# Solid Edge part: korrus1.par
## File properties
Author: Indrek
Template: Normal.par
Last saved by: Indrek
Revision: 14
Application: Solid Edge
Density: 7750,000 kg/m^3
Accuracy: 0,990
Material: Stainless Steel, 420
Face Style: Steel
Fill Style: ANSI32(Steel)
Virtual Style: Stainless steel
Coef. of Thermal Exp: 1e-05
Thermal Conductivity: 25.0
Specific Heat: 502.0
Modulus of Elasticity: 19994795300.0
Poission's Ratio: 0.29
Yield Stress: 344737850.0
Ultimate Stress: 655001915.0
Elongation: 0.0
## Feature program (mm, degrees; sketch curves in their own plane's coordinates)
make body feature "unnamed MakeBodyFeature 1"
sketch for "ExtrudedProtrusion_1" plane through (0, -392.2606, -246.4564) normal (0, -1, 0) x-axis (1, 0, 0)
  line (-90.7432, 47.25) -> (90.7431, 47.25)
extrude "ExtrudedProtrusion_1" add finite 189.0147 along +normal
sketch for "ExtrudedCutout_3" plane through (0, -290.6352, -199.2064) normal (0, 0, 1) x-axis (-1, 0, 0)
  line (145.5469, 330.1731) -> (178.3941, 235.8643)
  line (178.3941, 235.8643) -> (98.2107, 226.7853)
  line (-160.2715, 235.8643) -> (-98.1997, 222.207)
  line (-160.2715, 235.8643) -> (-57, 370.9489)
  line (-57, 370.9489) -> (145.5469, 330.1731)
extrude "ExtrudedCutout_3" cut finite 101.9235 along -normal
fillet "Round_2" radius 10
sketch used by "ExtrudedCutout_4" plane through (0, 0, -246.4564) normal (0, 1, 0) x-axis (-1, 0, 0)
extrude "ExtrudedCutout_4" cut finite 610.0099 along -normal
lofted protrusion "LoftedProtrusion_1"  StartTangentMagnitude1 = 1; EndTangentMagnitude1 = 1
sketch for "unnamed Cutout 1" #1 plane through (0, 0, -199.2064) normal (0, 0, -1) x-axis (0, 1, 0)
  line (260, 79.8569) -> (260, 10.0062)
  line (210, 10.0062) -> (260, 10.0062)
  line (210, 79.8569) -> (210, 10.0062)
  line (260, 79.8569) -> (210, 79.8569)
sketch for "unnamed Cutout 1" #2 plane through (0, 0, -199.2064) normal (0, 0, -1) x-axis (0, 1, 0)
  line (260, -79.8445) -> (260, -9.9938)
  line (210, -9.9938) -> (260, -9.9938)
  line (210, -79.8445) -> (210, -9.9938)
  line (260, -79.8445) -> (210, -79.8445)
sketch for "unnamed Cutout 1" #3 plane through (0, 0, -199.2064) normal (0, 0, -1) x-axis (0, 1, 0)
  line (190, -79.8445) -> (190, -9.9938)
  line (140, -9.9938) -> (190, -9.9938)
  line (140, -79.8445) -> (140, -9.9938)
  line (190, -79.8445) -> (140, -79.8445)
sketch for "unnamed Cutout 1" #4 plane through (0, 0, -199.2064) normal (0, 0, -1) x-axis (0, 1, 0)
  line (190, 79.8569) -> (190, 10.0062)
  line (140, 10.0062) -> (190, 10.0062)
  line (140, 10.0062) -> (140, 79.8569)
  line (190, 79.8569) -> (140, 79.8569)
sketch for "unnamed Cutout 1" #5 plane through (0, 0, -199.2064) normal (0, 0, -1) x-axis (0, 1, 0)
  line (120, 79.8569) -> (120, 10.0062)
  line (70, 10.0062) -> (120, 10.0062)
  line (70, 79.8569) -> (70, 10.0062)
  line (120, 79.8569) -> (70, 79.8569)
sketch for "unnamed Cutout 1" #6 plane through (0, 0, -199.2064) normal (0, 0, -1) x-axis (0, 1, 0)
  line (120, -79.8445) -> (120, -9.9938)
  line (70, -9.9938) -> (120, -9.9938)
  line (70, -79.8445) -> (70, -9.9938)
  line (120, -79.8445) -> (70, -79.8445)
extrude "unnamed Cutout 1" cut along +normal
sketch for "ExtrudedCutout_12" #1 plane through (0, 0, -199.2064) normal (0, 0, -1) x-axis (0, 1, 0)
  line (120, 79.8569) -> (120, 155.8794)
  line (120, 155.8794) -> (70, 155.8794)
  line (70, 155.8794) -> (70, 79.8569)
  line (70, 79.8569) -> (120, 79.8569)
sketch for "ExtrudedCutout_12" #2 plane through (0, 0, -199.2064) normal (0, 0, -1) x-axis (0, 1, 0)
  line (140, 79.8569) -> (140, 155.1744)
  line (140, 155.1744) -> (190, 155.1744)
  line (190, 155.1744) -> (190, 79.8569)
  line (140, 79.8569) -> (190, 79.8569)
sketch for "ExtrudedCutout_12" #3 plane through (0, 0, -199.2064) normal (0, 0, -1) x-axis (0, 1, 0)
  line (210, 79.8569) -> (210, 129.8569)
  line (210, 129.8569) -> (260, 129.8569)
  line (260, 129.8569) -> (260, 79.8569)
  line (210, 79.8569) -> (260, 79.8569)
sketch for "ExtrudedCutout_12" #4 plane through (0, 0, -199.2064) normal (0, 0, -1) x-axis (0, 1, 0)
  line (120, -79.8445) -> (120, -155.867)
  line (120, -155.867) -> (70, -155.867)
  line (70, -155.867) -> (70, -79.8445)
  line (70, -79.8445) -> (120, -79.8445)
sketch for "ExtrudedCutout_12" #5 plane through (0, 0, -199.2064) normal (0, 0, -1) x-axis (0, 1, 0)
  line (140, -79.8445) -> (140, -155.162)
  line (140, -155.162) -> (190, -155.162)
  line (190, -155.162) -> (190, -79.8445)
  line (140, -79.8445) -> (190, -79.8445)
sketch for "ExtrudedCutout_12" #6 plane through (0, 0, -199.2064) normal (0, 0, -1) x-axis (0, 1, 0)
  line (260, -129.8445) -> (260, -79.8445)
  line (210, -79.8445) -> (260, -79.8445)
  line (210, -79.8445) -> (210, -129.8445)
  line (210, -129.8445) -> (260, -129.8445)
extrude "ExtrudedCutout_12" cut finite 102.1796 along +normal
sketch used by "ExtrudedProtrusion_3" plane through (-9.9938, 95, -273.5848) normal (-1, 0, 0) x-axis (0, 0, -1)
extrude "ExtrudedProtrusion_3" add finite 1 along +normal
Other named dimensions: "OffsetSurface_2": Distance = 6 mm | "OffsetSurface_4": Distance = 3.175 mm
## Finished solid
Body 1: sheet body, 1 face, 4 edges, 4 vertices.
  Faces by surface: offset 1
  Edges by curve: curve on surface 4
Body 2: sheet body, 3 faces, 12 edges, 10 vertices.
  Faces by surface: offset 3
  Edges by curve: curve on surface 12
Body 3: solid body, 41 faces, 115 edges, 76 vertices.
  Faces by surface: plane 29, offset 6, spline 3, blend 1, cylinder 1, swept 1
  Edges by curve: intersection 70, line 32, spline 8, ellipse 3, circle 1, curve on surface 1
Body 4: solid body, 4 faces, 6 edges, 4 vertices.
  Faces by surface: plane 3, spline 1
  Edges by curve: line 2, spline 2, curve on surface 1, ellipse 1
Bounding box of the edges (mm; curved faces can reach further): 437.086 x 1070.680 x 94.500, from (-218.5431, -581.2753, -293.7064) to (218.5431, 489.4051, -199.2064).
Cylindrical faces by radius (mm): R106.0217 x1
Planar faces by outward normal: +x 6, +y 8, +z 3, -x 7, -y 7, oblique 1
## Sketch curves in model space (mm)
line (-9.9938, 70, -276.9892) -> (-9.9938, 71, -276.9892)
line (-9.9938, 71, -276.9892) -> (-9.9938, 71, -277.9892)
line (-9.9938, 71, -277.9892) -> (-9.9938, 70, -277.9892)
line (-9.9938, 70, -277.9892) -> (-9.9938, 70, -276.9892)
line (-79.8445, 120, -199.2064) -> (-9.9938, 120, -199.2064)
line (-79.8445, 120, -199.2064) -> (-79.8445, 70, -199.2064)
line (-79.8445, 70, -199.2064) -> (-9.9938, 70, -199.2064)
line (-9.9938, 70, -199.2064) -> (-9.9938, 120, -199.2064)
line (79.8569, 120, -199.2064) -> (10.0062, 120, -199.2064)
line (79.8569, 120, -199.2064) -> (79.8569, 70, -199.2064)
line (79.8569, 70, -199.2064) -> (10.0062, 70, -199.2064)
line (10.0062, 70, -199.2064) -> (10.0062, 120, -199.2064)
line (-9.9938, 210, -199.2064) -> (-9.9938, 260, -199.2064)
line (-79.8445, 210, -199.2064) -> (-9.9938, 210, -199.2064)
line (-79.8445, 260, -199.2064) -> (-79.8445, 210, -199.2064)
line (-79.8445, 260, -199.2064) -> (-9.9938, 260, -199.2064)
line (-9.9938, 140, -199.2064) -> (-9.9938, 190, -199.2064)
line (-79.8445, 190, -199.2064) -> (-9.9938, 190, -199.2064)
line (-79.8445, 190, -199.2064) -> (-79.8445, 140, -199.2064)
line (-79.8445, 140, -199.2064) -> (-9.9938, 140, -199.2064)
line (10.0062, 210, -199.2064) -> (10.0062, 260, -199.2064)
line (79.8569, 260, -199.2064) -> (10.0062, 260, -199.2064)
line (79.8569, 260, -199.2064) -> (79.8569, 210, -199.2064)
line (79.8569, 210, -199.2064) -> (10.0062, 210, -199.2064)
line (-108.2634, 280, -199.2064) -> (-108.2634, 330, -199.2064)
line (-108.2634, 330, -199.2064) -> (-9.9763, 330, -199.2064)
line (-9.9763, 330, -199.2064) -> (-9.9763, 280, -199.2064)
line (-9.9763, 280, -199.2064) -> (-22.3394, 280, -199.2064)
line (-22.3394, 280, -199.2064) -> (-108.2634, 280, -199.2064)
line (-89.9763, 350, -199.2064) -> (-89.9763, 400, -199.2064)
line (-89.9763, 400, -199.2064) -> (-9.9763, 400, -199.2064)
line (-9.9763, 400, -199.2064) -> (-9.9763, 350, -199.2064)
line (-9.9763, 350, -199.2064) -> (-89.9763, 350, -199.2064)
line (79.8569, 190, -199.2064) -> (10.0062, 190, -199.2064)
line (79.8569, 190, -199.2064) -> (79.8569, 140, -199.2064)
line (10.0062, 140, -199.2064) -> (79.8569, 140, -199.2064)
line (10.0062, 140, -199.2064) -> (10.0062, 190, -199.2064)
line (108.2758, 280, -199.2064) -> (108.2758, 330, -199.2064)
line (108.2758, 330, -199.2064) -> (9.9887, 330, -199.2064)
line (9.9887, 330, -199.2064) -> (9.9887, 280, -199.2064)
line (9.9887, 280, -199.2064) -> (22.3518, 280, -199.2064)
line (22.3518, 280, -199.2064) -> (108.2758, 280, -199.2064)
line (89.9887, 350, -199.2064) -> (89.9887, 400, -199.2064)
line (89.9887, 400, -199.2064) -> (9.9887, 400, -199.2064)
line (9.9887, 400, -199.2064) -> (9.9887, 350, -199.2064)
line (9.9887, 350, -199.2064) -> (89.9887, 350, -199.2064)
line (254.9026, 0, -273.7064) -> (254.9026, 0, -173.0843)
line (254.9026, 0, -173.0843) -> (-245.3683, 0, -173.0843)
line (-245.3683, 0, -173.0843) -> (-245.3683, 0, -273.7064)
line (-245.3683, 0, -273.7064) -> (254.9026, 0, -273.7064)
ellipse centre (0, 0, -225.3386) radii 218.5431, 68.3678 from (-154.455, 0, -273.7064) through (6.3522, 0, -293.6775) to (154.455, 0, -273.7064)
line (-154.4552, 0, -273.7064) -> (154.4552, 0, -273.7064)
ellipse centre (-0.0679, 485.107, -199.453) radii 10, 2.6347
ellipse centre (0, -392.2606, -225.3386) radii 98.1997, 68.3678 from (0.0062, -392.2606, -293.7064) through (83.2252, -392.2606, -261.6269) to (90.7431, -392.2606, -199.2064)
line (-162.6174, 0, -199.2064) -> (-162.6174, 50, -199.2064)
line (-162.6174, 50, -199.2064) -> (-9.9938, 50, -199.2064)
line (-9.9938, 50, -199.2064) -> (-10.1927, 0, -199.2064)
line (-10.1927, 0, -199.2064) -> (-162.6174, 0, -199.2064)
line (-79.8445, 70, -199.2064) -> (-79.8445, 120, -199.2064)
line (-79.8445, 120, -199.2064) -> (-155.867, 120, -199.2064)
line (-155.867, 120, -199.2064) -> (-155.867, 70, -199.2064)
line (-155.867, 70, -199.2064) -> (-79.8445, 70, -199.2064)
line (-129.8445, 260, -199.2064) -> (-79.8445, 260, -199.2064)
line (-129.8445, 210, -199.2064) -> (-129.8445, 260, -199.2064)
line (-79.8445, 210, -199.2064) -> (-129.8445, 210, -199.2064)
line (-79.8445, 210, -199.2064) -> (-79.8445, 260, -199.2064)
line (-155.162, 140, -199.2064) -> (-155.162, 190, -199.2064)
line (-155.162, 190, -199.2064) -> (-79.8445, 190, -199.2064)
line (-79.8445, 140, -199.2064) -> (-79.8445, 190, -199.2064)
line (-79.8445, 140, -199.2064) -> (-155.162, 140, -199.2064)
line (162.6298, 0, -199.2064) -> (162.6298, 50, -199.2064)
line (162.6298, 50, -199.2064) -> (10.0062, 50, -199.2064)
line (10.0062, 50, -199.2064) -> (10.2051, 0, -199.2064)
line (10.2051, 0, -199.2064) -> (162.6298, 0, -199.2064)
line (79.8569, 70, -199.2064) -> (79.8569, 120, -199.2064)
line (79.8569, 120, -199.2064) -> (155.8794, 120, -199.2064)
line (155.8794, 120, -199.2064) -> (155.8794, 70, -199.2064)
line (155.8794, 70, -199.2064) -> (79.8569, 70, -199.2064)
line (129.8569, 260, -199.2064) -> (79.8569, 260, -199.2064)
line (129.8569, 210, -199.2064) -> (129.8569, 260, -199.2064)
line (79.8569, 210, -199.2064) -> (129.8569, 210, -199.2064)
line (79.8569, 210, -199.2064) -> (79.8569, 260, -199.2064)
line (155.1744, 140, -199.2064) -> (155.1744, 190, -199.2064)
line (155.1744, 190, -199.2064) -> (79.8569, 190, -199.2064)
line (79.8569, 140, -199.2064) -> (79.8569, 190, -199.2064)
line (79.8569, 140, -199.2064) -> (155.1744, 140, -199.2064)
ellipse centre (0, -392.2606, -225.3386) radii 98.1997, 68.3678 from (-90.7431, -392.2606, -199.2064) through (5.838, -392.2606, -293.5855) to (90.7431, -392.2606, -199.2064)
line (-90.7431, -392.2606, -199.2064) -> (90.7431, -392.2606, -199.2064)
line (44.3041, -171.7493, -199.2064) -> (181.7265, -171.7493, -199.2064)
ellipse centre (0, -171.7493, -225.3386) radii 196.6594, 68.3678 from (-181.7265, -171.7493, -199.2064) through (11.6914, -171.7493, -293.5855) to (181.7265, -171.7493, -199.2064)
line (-181.7265, -171.7493, -199.2064) -> (181.7265, -171.7493, -199.2064)
ellipse centre (0, 0, -225.3386) radii 218.5431, 68.3678 from (-201.9485, 0, -199.2064) through (12.9924, 0, -293.5855) to (201.9485, 0, -199.2064)
line (201.9485, 0, -199.2064) -> (-201.9485, 0, -199.2064)
spline (0.0062, 372.8756, -293.7064) -> (0.0043, 454.9346, -265.2954) -> (0, 484.7091, -199.4524)
line (0.0062, 0, -293.7064) -> (0.0062, 372.8756, -293.7064)
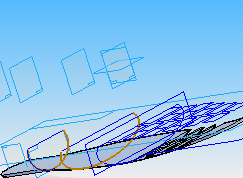
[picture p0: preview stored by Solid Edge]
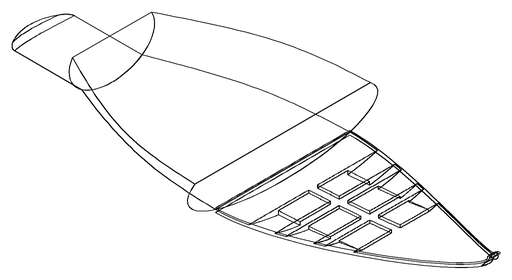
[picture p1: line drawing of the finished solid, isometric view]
